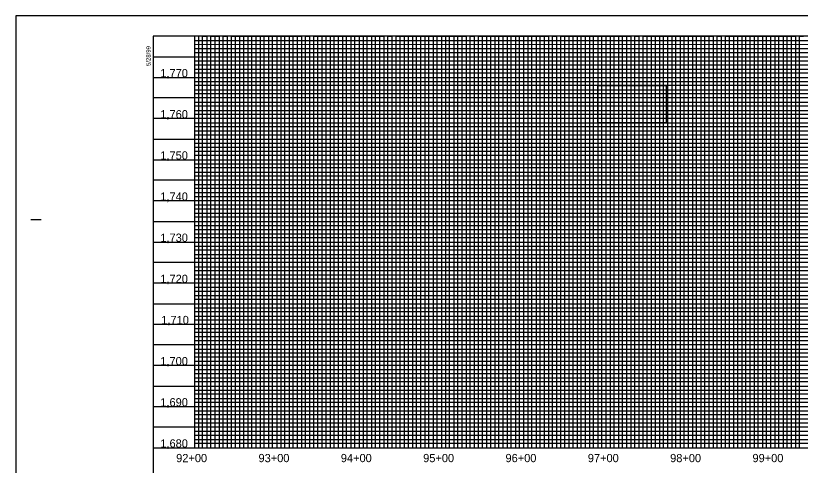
# Model space of a CAD drawing. Extents: x 505602 to 507286, y 483109 to 484209.
# Drawn here: x 505602 to 506555, y 483662 to 484209 of the extents above; entities that cross this region are included whole.
import ezdxf

# ---------------------------------------------------------------- set-up
doc = ezdxf.new("R2010")
doc.units = 0
for name, color, linetype in [('Exist Vertical Profile Vertical Axis Label', 7, 'Continuous'), ('Prop Grid Mask', 7, 'Continuous'), ('Sheet Layout Profile Border Port 1', 7, 'Continuous'), ('Sheet Plot Border Outside CELL', 7, 'Continuous'), ('Sheet Profile CELL', 7, 'Continuous'), ('Sheet Profile Grid Major CELL', 7, 'Continuous'), ('Sheet Profile Grid Middle CELL', 7, 'Continuous'), ('Sheet Profile Grid Minor CELL', 7, 'Continuous')]:
    doc.layers.add(name, color=color, linetype=linetype)

msp = doc.modelspace()

# ---------------------------------------------------------------- linework, layer by layer
at = {"layer": 'Prop Grid Mask'}
msp.add_lwpolyline([(506309.08, 484123.71), (506392.18, 484123.71), (506392.18, 484078.71), (506309.08, 484078.71)], close=True, dxfattribs=at)
at = {"layer": 'Sheet Layout Profile Border Port 1'}
msp.add_lwpolyline([(505819.08, 484183.71), (505819.08, 483683.71), (507019.08, 483683.71), (507019.08, 484022.66), (507019.08, 484022.66), (507019.08, 484183.71)], close=True, dxfattribs=at)
at = {"layer": 'Sheet Plot Border Outside CELL'}
msp.add_lwpolyline([(505602.08, 483108.71), (507286.08, 483108.71), (507286.08, 484208.71), (505602.08, 484208.71)], close=True, dxfattribs=at)
at = {"layer": 'Sheet Profile CELL'}
for p, q in [((505620.58, 483961.21), (505633.08, 483961.21)), ((505769.08, 483683.71), (507269.08, 483683.71))]:
    msp.add_line(p, q, dxfattribs=at)
msp.add_lwpolyline([(507269.08, 484183.71), (505769.08, 484183.71), (505769.08, 483133.71), (507269.08, 483133.71)], close=True, dxfattribs=at)
at = {"layer": 'Sheet Profile Grid Major CELL'}
for points in [[(505819.08, 484183.71), (505819.08, 483683.71), (505869.08, 483683.71), (505869.08, 484183.71), (505919.08, 484183.71), (505919.08, 483683.71), (505969.08, 483683.71), (505969.08, 484183.71), (506019.08, 484183.71), (506019.08, 483683.71), (506069.08, 483683.71), (506069.08, 484183.71), (506119.08, 484183.71), (506119.08, 483683.71), (506169.08, 483683.71), (506169.08, 484183.71), (506219.08, 484183.71), (506219.08, 483683.71), (506269.08, 483683.71), (506269.08, 484183.71), (506319.08, 484183.71), (506319.08, 483683.71), (506369.08, 483683.71), (506369.08, 484183.71), (506419.08, 484183.71), (506419.08, 483683.71), (506469.08, 483683.71), (506469.08, 484183.71), (506519.08, 484183.71), (506519.08, 483683.71), (506569.08, 483683.71)], [(505769.08, 484133.71), (507069.08, 484133.71)], [(507069.08, 484083.71), (505769.08, 484083.71), (505769.08, 484033.71), (507069.08, 484033.71)], [(507269.08, 483983.71), (505769.08, 483983.71), (505769.08, 483933.71), (507269.08, 483933.71)], [(507269.08, 483883.71), (505769.08, 483883.71), (505769.08, 483833.71), (507269.08, 483833.71)], [(507269.08, 483783.71), (505769.08, 483783.71), (505769.08, 483783.71), (505769.08, 483733.71), (507269.08, 483733.71)]]:
    msp.add_lwpolyline(points, dxfattribs=at)
at = {"layer": 'Sheet Profile Grid Middle CELL'}
msp.add_line((505769.08, 484158.71), (507069.03, 484158.71), dxfattribs=at)
for points in [[(505844.08, 484183.71), (505844.08, 483683.71), (505894.08, 483683.71), (505894.08, 484183.71), (505944.08, 484183.71), (505944.08, 483683.71), (505994.08, 483683.71), (505994.08, 484183.71), (506044.08, 484183.71), (506044.08, 483683.71), (506094.08, 483683.71), (506094.08, 484183.71), (506144.08, 484183.71), (506144.08, 483683.71), (506194.08, 483683.71), (506194.08, 484183.71), (506244.08, 484183.71), (506244.08, 483683.71), (506294.08, 483683.71), (506294.08, 484183.71), (506344.08, 484183.71), (506344.08, 483683.71), (506394.08, 483683.71), (506394.08, 483683.71), (506394.08, 484183.71), (506444.08, 484183.71), (506444.08, 483683.71), (506494.08, 483683.71), (506494.08, 484183.71), (506544.08, 484183.71), (506544.08, 483683.71), (506594.08, 483683.71)], [(507069.08, 484108.71), (505769.08, 484108.71), (505769.08, 484058.71), (507069.08, 484058.71)], [(507269.08, 484008.71), (505769.08, 484008.71), (505769.08, 483958.71), (507094.08, 483958.71)], [(507269.08, 483908.71), (505769.08, 483908.71), (505769.08, 483858.71), (507269.08, 483858.71)], [(507269.08, 483808.71), (505769.08, 483808.71), (505769.08, 483758.71), (507269.08, 483758.71)], [(507269.08, 483708.71), (505769.08, 483708.71)]]:
    msp.add_lwpolyline(points, dxfattribs=at)
at = {"layer": 'Sheet Profile Grid Minor CELL'}
for p, q in [((505819.08, 484178.71), (507069.08, 484178.71)), ((505819.08, 484173.71), (505819.08, 484173.71)), ((507069.08, 484173.71), (505819.08, 484173.36)), ((505819.08, 484168.71), (507069.08, 484168.71)), ((507069.03, 484048.71), (505819.08, 484048.71)), ((507069.08, 484043.71), (505819.08, 484043.71)), ((507069.08, 484038.71), (505819.08, 484038.71)), ((505819.08, 484028.71), (507069.08, 484028.71)), ((507069.08, 484023.71), (505819.08, 484023.71)), ((505819.08, 484018.71), (507219.08, 484018.71)), ((507219.08, 483998.71), (505819.08, 483998.71)), ((505819.08, 483993.71), (507219.08, 483993.71)), ((507219.08, 483973.71), (505819.08, 483973.71)), ((505819.08, 483968.71), (507219.08, 483968.71)), ((507219.08, 483948.71), (505819.08, 483948.71)), ((505819.08, 483943.71), (507219.08, 483943.71)), ((507219.08, 483938.71), (505819.08, 483938.71)), ((505819.08, 483928.71), (507219.08, 483928.71)), ((507219.08, 483923.71), (505819.08, 483923.71)), ((505819.08, 483918.71), (507219.08, 483918.71)), ((507219.08, 483913.71), (505819.08, 483913.71)), ((505819.08, 483903.71), (507219.08, 483903.71)), ((507219.08, 483898.71), (505819.08, 483898.71)), ((505819.08, 483893.71), (507219.08, 483893.71)), ((507219.08, 483888.71), (505819.08, 483888.71)), ((505819.08, 483878.71), (507219.08, 483878.71)), ((507219.08, 483873.71), (505819.08, 483873.71)), ((505819.08, 483868.71), (507219.08, 483868.71)), ((507219.08, 483863.71), (505819.08, 483863.71)), ((505819.08, 483853.71), (507219.08, 483853.71)), ((507219.08, 483848.71), (505819.08, 483848.71)), ((505819.08, 483843.71), (507219.08, 483843.71)), ((507219.08, 483838.71), (505819.08, 483838.71)), ((505819.08, 483828.71), (507219.08, 483828.71)), ((507219.08, 483823.71), (505819.08, 483823.71)), ((505819.08, 483818.71), (507219.08, 483818.71)), ((507219.08, 483813.71), (505819.08, 483813.71)), ((505819.08, 483803.71), (507219.08, 483803.71)), ((507219.08, 483798.71), (505819.08, 483798.71)), ((507219.08, 483793.71), (505819.08, 483793.71)), ((507219.08, 483788.71), (505819.08, 483788.71)), ((505819.08, 483778.71), (507219.08, 483778.71)), ((507219.08, 483773.71), (505819.08, 483773.71)), ((505819.08, 483768.71), (507219.08, 483768.71)), ((507219.08, 483763.71), (505819.08, 483763.71)), ((505819.08, 483753.71), (507219.08, 483753.71)), ((507219.08, 483748.71), (505819.08, 483748.71)), ((505819.08, 483743.71), (507219.08, 483743.71)), ((507219.08, 483738.71), (505819.08, 483738.71)), ((505819.08, 483728.71), (507219.08, 483728.71)), ((507219.08, 483723.71), (505819.08, 483723.71)), ((505819.08, 483718.71), (507219.08, 483718.71)), ((507219.08, 483713.71), (505819.08, 483713.71)), ((505819.08, 483703.71), (507219.08, 483703.71)), ((507219.08, 483698.71), (505819.08, 483698.71)), ((505819.08, 483693.71), (507219.08, 483693.71))]:
    msp.add_line(p, q, dxfattribs=at)
for points in [[(505824.08, 484183.71), (505824.08, 483683.71), (505829.08, 483683.71), (505829.08, 484183.71), (505834.08, 484183.71), (505834.08, 483683.71), (505839.08, 483683.71), (505839.08, 484183.71), (505849.08, 484183.71), (505849.08, 483683.71), (505854.08, 483683.71), (505854.08, 484183.71), (505859.08, 484183.71), (505859.08, 483683.71), (505864.08, 483683.71), (505874.08, 483683.71), (505879.08, 483683.71), (505879.08, 484183.71), (505884.08, 484183.71), (505884.08, 483683.71), (505889.08, 483683.71), (505889.08, 484183.71), (505899.08, 484183.71), (505899.08, 483683.71), (505904.08, 483683.71), (505904.08, 484183.71), (505909.08, 484183.71), (505909.08, 483683.71), (505914.08, 483683.71), (505914.08, 484183.71), (505924.08, 484183.71), (505924.08, 483683.71), (505929.08, 483683.71), (505929.08, 484183.71), (505934.08, 484183.71), (505934.08, 483683.71), (505939.08, 483683.71), (505939.08, 484183.71), (505949.08, 484183.71), (505949.08, 483683.71), (505954.08, 483683.71), (505954.08, 484183.71), (505959.08, 484183.71), (505959.08, 483683.71), (505964.08, 483683.71), (505964.08, 484183.71), (505974.08, 484183.71), (505974.08, 483683.71), (505979.08, 483683.71), (505979.08, 484183.71), (505984.08, 484183.71), (505984.08, 483683.71), (505989.08, 483683.71), (505989.08, 484183.71), (505999.08, 484183.71), (505999.08, 483683.71), (506004.08, 483683.71), (506004.08, 484183.71), (506009.08, 484183.71), (506009.08, 483683.71), (506014.08, 483683.71), (506014.08, 484183.71), (506024.08, 484183.71), (506024.08, 483683.71), (506029.08, 483683.71), (506029.08, 484183.71), (506034.08, 484183.71), (506034.08, 483683.71)], [(505864.08, 483683.71), (505864.08, 484183.71), (505874.08, 484183.71), (505874.08, 483683.71)], [(506034.08, 483683.71), (506039.08, 483683.71), (506039.08, 484183.71), (506049.08, 484183.71), (506049.08, 483683.71), (506054.08, 483683.71), (506054.08, 484183.71), (506059.08, 484183.71), (506059.08, 483683.71), (506064.08, 483683.71), (506064.08, 484183.71), (506074.08, 484183.71), (506074.08, 483683.71), (506079.08, 483683.71), (506079.08, 484183.71), (506084.08, 484183.71), (506084.08, 483683.71), (506089.08, 483683.71), (506089.08, 484183.71), (506099.08, 484183.71), (506099.08, 483683.71), (506104.08, 483683.71), (506104.08, 484183.71), (506109.08, 484183.71), (506109.08, 483683.71), (506114.08, 483683.71), (506114.08, 484183.71), (506124.08, 484183.71), (506124.08, 483683.71), (506129.08, 483683.71), (506129.08, 484183.71), (506134.08, 484183.71), (506134.08, 483683.71), (506139.08, 483683.71), (506139.08, 484183.71), (506149.08, 484183.71), (506149.08, 483683.71), (506154.08, 483683.71), (506154.08, 484183.71), (506159.08, 484183.71), (506159.08, 483683.71), (506164.08, 483683.71), (506164.08, 484183.71), (506174.08, 484183.71), (506174.08, 483683.71), (506179.08, 483683.71), (506179.08, 484183.71), (506184.08, 484183.71), (506184.08, 483683.71), (506189.08, 483683.71), (506189.08, 484183.71), (506199.08, 484183.71), (506199.08, 483683.71), (506204.08, 483683.71), (506204.08, 484183.71), (506209.08, 484183.71), (506209.08, 483683.71), (506214.08, 483683.71), (506214.08, 484183.71), (506224.08, 484183.71), (506224.08, 483683.71), (506229.08, 483683.71), (506229.08, 484183.71), (506234.08, 484183.71), (506234.08, 483683.71), (506239.08, 483683.71), (506239.08, 484183.71), (506249.08, 484183.71), (506249.08, 483683.71), (506254.08, 483683.71), (506254.08, 484183.71), (506259.08, 484183.71), (506259.08, 483683.71), (506264.08, 483683.71), (506264.08, 484183.71), (506274.08, 484183.71), (506274.08, 483683.71), (506279.08, 483683.71), (506279.08, 484183.71), (506284.08, 484183.71), (506284.08, 483683.71), (506289.08, 483683.71), (506289.08, 484183.71), (506299.08, 484183.71), (506299.08, 483683.71), (506304.08, 483683.71), (506304.08, 484183.71), (506309.08, 484183.71), (506309.08, 483683.71), (506314.08, 483683.71), (506314.08, 484183.71), (506324.08, 484183.71), (506324.08, 483683.71), (506329.08, 483683.71), (506329.08, 484183.71), (506334.08, 484183.71), (506334.08, 483683.71), (506339.08, 483683.71), (506339.08, 484183.71), (506349.08, 484183.71)], [(506349.08, 484183.71), (506349.08, 483683.71), (506354.08, 483683.71), (506354.08, 484183.71), (506359.08, 484183.71), (506359.08, 483683.71), (506364.08, 483683.71), (506364.08, 484183.71), (506374.08, 484183.71), (506374.08, 483683.71), (506379.08, 483683.71), (506379.08, 484183.71), (506384.08, 484183.71), (506384.08, 483683.71), (506389.08, 483683.71), (506389.08, 484183.71), (506399.08, 484183.71), (506399.08, 483683.71), (506404.08, 483683.71), (506404.08, 484183.71), (506409.08, 484183.71), (506409.08, 483683.71), (506414.08, 483683.71), (506414.08, 484183.71), (506424.08, 484183.71), (506424.08, 483683.71), (506429.08, 483683.71), (506429.08, 484183.71), (506434.08, 484183.71), (506434.08, 483683.71), (506439.08, 483683.71), (506439.08, 484183.71), (506449.08, 484183.71), (506449.08, 483683.71), (506454.08, 483683.71), (506454.08, 484183.71), (506459.08, 484183.71), (506459.08, 483683.71), (506464.08, 483683.71), (506464.08, 484183.71), (506474.08, 484183.71), (506474.08, 483683.71), (506474.08, 483683.71), (506479.08, 483683.71), (506479.08, 484183.71), (506484.08, 484183.71), (506484.08, 483683.71), (506489.08, 483683.71), (506489.08, 484183.71), (506499.08, 484183.71), (506499.08, 483683.71), (506504.08, 483683.71), (506504.08, 484183.71), (506509.08, 484183.71), (506509.08, 483683.71), (506514.08, 483683.71), (506514.08, 484183.71), (506524.08, 484183.71), (506524.08, 483683.71), (506529.08, 483683.71), (506529.08, 484183.71), (506534.08, 484183.71), (506534.08, 483683.71), (506539.08, 483683.71), (506539.08, 484183.71), (506549.08, 484183.71), (506549.08, 483683.71), (506554.08, 483683.71), (506554.08, 484183.71), (506559.08, 484183.71)], [(507069.08, 484163.71), (505819.08, 484163.71), (505819.08, 484153.71), (507069.08, 484153.71)], [(507069.03, 484148.71), (505819.08, 484148.71), (505819.08, 484143.71), (507069.08, 484143.71)], [(507069.08, 484138.71), (505819.08, 484138.71), (505819.08, 484128.71), (507069.08, 484128.71)], [(507069.08, 484123.71), (505819.08, 484123.71), (505819.08, 484118.71), (507069.08, 484118.71)], [(507069.08, 484113.71), (505819.08, 484113.71), (505819.08, 484103.71), (507069.08, 484103.71)], [(507069.08, 484098.71), (505819.08, 484098.71), (505819.08, 484093.71), (507069.08, 484093.71)], [(507069.08, 484088.71), (505819.08, 484088.71), (505819.08, 484078.71), (507069.08, 484078.71)], [(507069.08, 484073.61), (505819.18, 484073.61), (505819.18, 484068.71), (507069.08, 484068.71)], [(507069.08, 484063.71), (505819.08, 484063.71), (505819.08, 484053.71), (507069.08, 484053.71)], [(507219.08, 484013.71), (505819.08, 484013.71), (505819.08, 484003.71), (507219.08, 484003.71)], [(507219.08, 483988.71), (505819.08, 483988.71), (505819.08, 483978.71), (507219.08, 483978.71)], [(507219.08, 483963.71), (505819.08, 483963.71), (505819.08, 483953.71), (507219.08, 483953.71)], [(507219.08, 483688.71), (505819.08, 483688.71)]]:
    msp.add_lwpolyline(points, dxfattribs=at)

# ---------------------------------------------------------------- texts
at = {"layer": 'Exist Vertical Profile Vertical Axis Label'}
for s, p in [('1,770', (505777.78, 484133.96)), ('1,760', (505777.78, 484083.96)), ('1,750', (505777.78, 484033.96)), ('1,740', (505777.78, 483983.96)), ('1,730', (505777.78, 483933.96)), ('1,720', (505777.78, 483883.96)), ('1,710', (505778.97, 483833.96)), ('1,700', (505777.78, 483783.96)), ('1,690', (505777.78, 483733.96)), ('1,680', (505777.78, 483683.96)), ('92+00', (505797.01, 483666.21)), ('93+00', (505897.01, 483666.21)), ('94+00', (505997.01, 483666.21)), ('95+00', (506097.01, 483666.21)), ('96+00', (506197.01, 483666.21)), ('97+00', (506297.01, 483666.21)), ('98+00', (506397.01, 483666.21)), ('99+00', (506497.01, 483666.21))]:
    msp.add_text(s, height=10, dxfattribs=at).set_placement(p)
at = {"layer": 'Sheet Profile CELL'}
msp.add_text('5/28/99', height=5.25, rotation=90, dxfattribs=at).set_placement((505765.84, 484147.62))

doc.saveas('drawing.dxf')
